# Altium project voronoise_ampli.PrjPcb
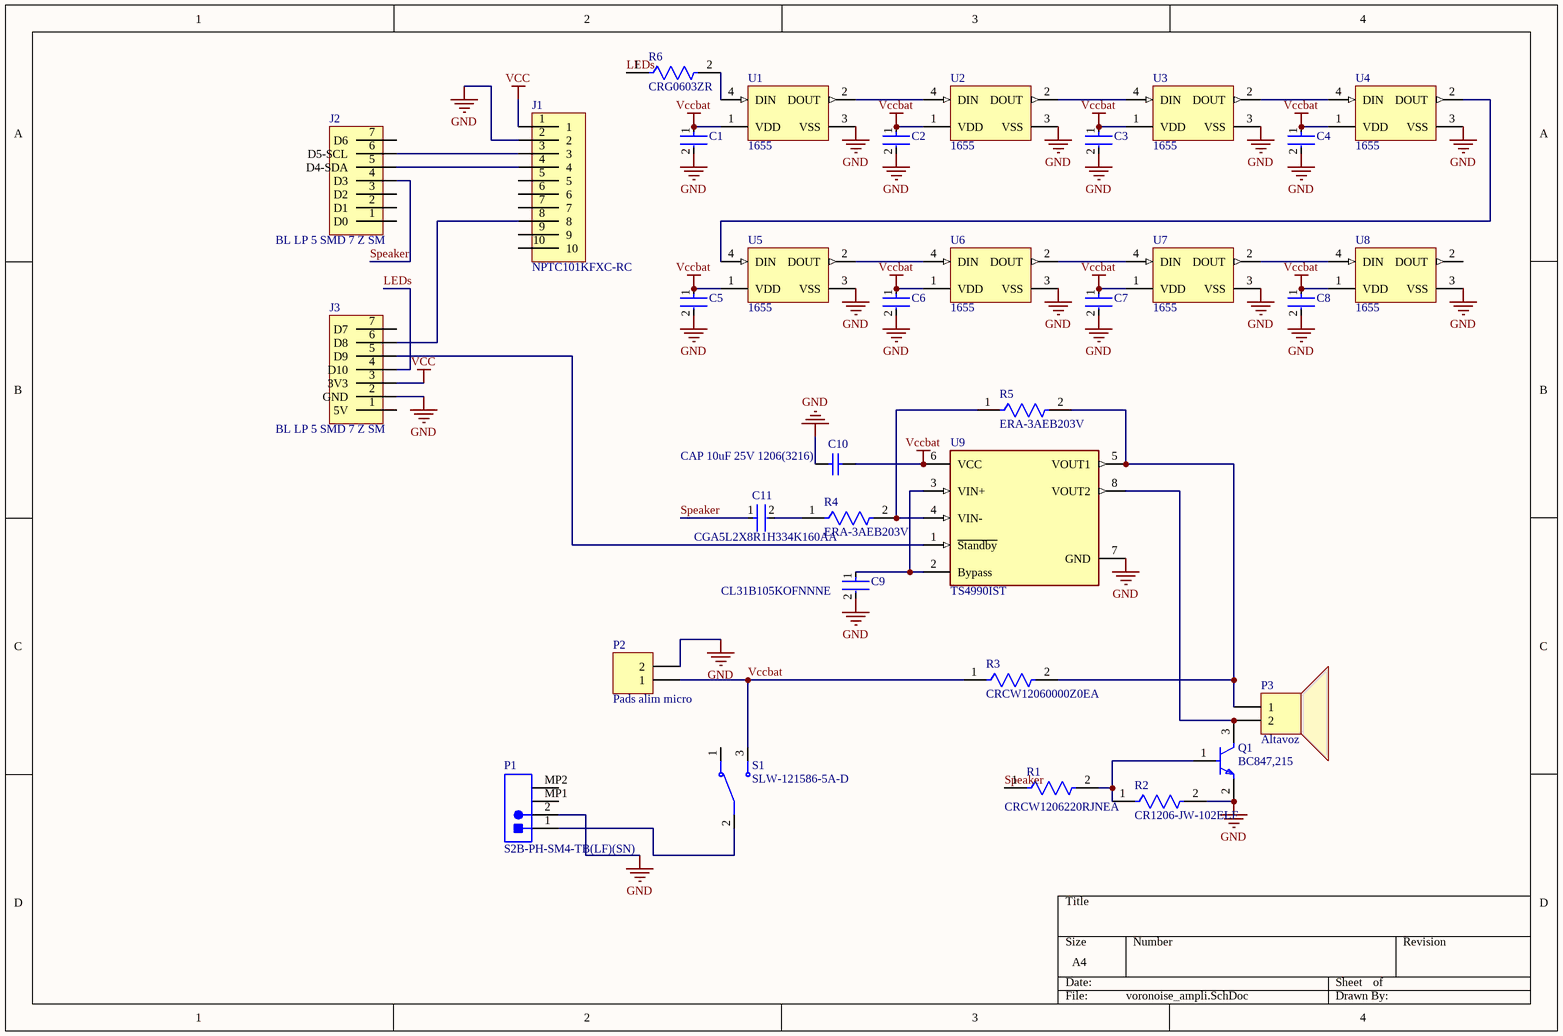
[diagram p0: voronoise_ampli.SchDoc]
1 sheet, 34 parts. Net scope: global (net labels, ports and power ports of the same name join across sheets).
Board file: voronoise_ampli.PcbDoc

## Sheet voronoise_ampli.SchDoc
size A4; SheetNumber: 1; SheetTotal: 1

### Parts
C1  C0603C104K4RACTU  [FP-C0603C-CF-MFG]  (value not drawn)
C2  C0603C104K4RACTU  [FP-C0603C-CF-MFG]  (value not drawn)
C3  C0603C104K4RACTU  [FP-C0603C-CF-MFG]  (value not drawn)
C4  C0603C104K4RACTU  [FP-C0603C-CF-MFG]  (value not drawn)
C5  C0603C104K4RACTU  [FP-C0603C-CF-MFG]  (value not drawn)
C6  C0603C104K4RACTU  [FP-C0603C-CF-MFG]  (value not drawn)
C7  C0603C104K4RACTU  [FP-C0603C-CF-MFG]  (value not drawn)
C8  C0603C104K4RACTU  [FP-C0603C-CF-MFG]  (value not drawn)
C9  CL31B105KOFNNNE  [FP-CL31-IPC_C]
C10  CAP 10uF 25V 1206(3216)  [CAPC1206(3216)190_N]
C11  CGA5L2X8R1H334K160AA  [FP-CGA5L-0_3-0_1-MFG]
J1  NPTC101KFXC-RC  [NPTC101KFXC-RC]
J2  BL LP 5 SMD 7 Z SM  [BL LP 5 SMD 7 Z SM]
J3  BL LP 5 SMD 7 Z SM  [BL LP 5 SMD 7 Z SM]
P1  S2B-PH-SM4-TB(LF)(SN)  [JST- S2B-PH-SM4-TB(LF)(SN)-2_V]
P2  Pads alim micro  [HDR1X2]
P3  Altavoz  [HDR1X2]
Q1  BC847,215  [FP-SOT23-MFG]
R1  CRCW1206220RJNEA  [FP-CRCW1206-e3-IPC_C]
R2  CR1206-JW-102ELF  [FP-CR1206-IPC_C]
R3  CRCW12060000Z0EA  [FP-CRCW1206-e3-IPC_C]
R4  ERA-3AEB203V  [FP-ERA3A-MFG]
R5  ERA-3AEB203V  [FP-ERA3A-MFG]
R6  CRG0603ZR  [FP-CRG0603-IPC_C]
S1  SLW-121586-5A-D  [SW_SLW-121586-5A-D]
U1  1655  [ADA-RGB-1655_V]
U2  1655  [ADA-RGB-1655_V]
U3  1655  [ADA-RGB-1655_V]
U4  1655  [ADA-RGB-1655_V]
U5  1655  [ADA-RGB-1655_V]
U6  1655  [ADA-RGB-1655_V]
U7  1655  [ADA-RGB-1655_V]
U8  1655  [ADA-RGB-1655_V]
U9  TS4990IST  [FP-MiniSO-8-IPC_C]

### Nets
GND: C1.2 C2.2 C3.2 C4.2 C5.2 C6.2 C7.2 C8.2 C9.2 C10.1 J1.2 J3.2(GND) P1.2 P2.2 Q1.2(E) R2.2 U1.3(VSS) U2.3(VSS) U3.3(VSS) U4.3(VSS) U5.3(VSS) U6.3(VSS) U7.3(VSS) U8.3(VSS) U9.7(GND)
VCC: J1.1 J3.3(3V3)
Vccbat: C1.1 C2.1 C3.1 C4.1 C5.1 C6.1 C7.1 C8.1 C10.2 P2.1 R3.1 S1.3 U1.1(VDD) U2.1(VDD) U3.1(VDD) U4.1(VDD) U5.1(VDD) U6.1(VDD) U7.1(VDD) U8.1(VDD) U9.6(VCC)
LEDs: J3.4(D10) R6.1
Speaker: C11.1 J2.4(D3) R1.1
NetC9_1: C9.1 U9.2(Bypass) U9.3(VIN+)
NetC11_2: C11.2 R4.1
NetJ1_3: J1.3 J2.6(D5-SCL)
NetJ1_4: J1.4 J2.5(D4-SDA)
NetJ1_8: J1.8 J3.6(D8)
NetJ3_5: J3.5(D9) U9.1(~{Standby})
NetP1_1: P1.1 S1.2
NetP3_1: P3.1 R3.2 R5.2 U9.5(VOUT1)
NetP3_2: P3.2 Q1.3(C) U9.8(VOUT2)
NetQ1_1: Q1.1(B) R1.2 R2.1
NetR4_2: R4.2 R5.1 U9.4(VIN-)
NetR6_2: R6.2 U1.4(DIN)
NetU1_2: U1.2(DOUT) U2.4(DIN)
NetU2_2: U2.2(DOUT) U3.4(DIN)
NetU3_2: U3.2(DOUT) U4.4(DIN)
NetU4_2: U4.2(DOUT) U5.4(DIN)
NetU5_2: U5.2(DOUT) U6.4(DIN)
NetU6_2: U6.2(DOUT) U7.4(DIN)
NetU7_2: U7.2(DOUT) U8.4(DIN)

Not connected (* = marked no-connect by the designer): J1 5 6 7 9 10; J2 1(D0) 2(D1) 3(D2) 7(D6); J3 1(5V) 7(D7); P1 MP1 MP2; S1 1; U8 2(DOUT)

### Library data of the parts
C1-C8 = CMP-2006-03811-3: Capacitor; Ceramic; Cap; .100uF; Tol 10%; SMT; Vol-Rtg 16V; X7R; Tape and Reel; Manufacturer: KEMET; Value: 0.10 μF; Temperature Coefficient: 30ppm/°C; Automotive Grade: Grade 1; Tolerance: 0.1; Description: C0603 0.10 μF X7R 30ppm/°C 10.00% 16 V
C9 = CMP-13271-000025-1: Cap Ceramic 1uF 16V X7R ±10% SMD 1206 +125°C Embossed T/R
C10 = CMP-1037-04981-1: CAP 10uF 25V -20% to +80% 1206 (3216 Metric) Thickness 1.9mm SMD; Case-EIA: 1206; Case-Metric: 3216
C11 = CMP-08246-001129-1: Cap Ceramic 330nF 50V X8R 10% Pad SMD 1206 +150°C Automotive T/R
J1 = NPTC101KFXC-RC: Sullins Connector Solutions 10 pin female header. SMD.
J2 J3 = BL LP 5 SMD 7 Z SM: Fischer elektronik 7 pin female header. SMD.
P1 = CMP-1755-00001-1: Male Header, Pitch 2 mm, 1 x 2 Position, Height 5.5 mm, -25 to 85 degC, RoHS, Tape and Reel; Current Rating: 3 A
P2 P3 = Header 2: Header, 2-Pin
Q1 = CMP-14406-000009-1: TRANS NPN 45V 0.1A SOT23; Manufacturer: Nexperia; Max Collector Current: 100mA; Hfe Testvce: 5V; Hfe Testic: 2mA; Number Of Npn: 1; Max Junction Temp: +150°C; Collector Base Voltage: 50V; Hfe Max: 800; Power Dissipation: 250mW; Emitter Base Voltage: 6V; Automotive Grade: Grade 0; Gain Bandwidth Product: 100MHz; Rthja Max: 500K/W; Collector Emitter Saturation Voltage: 200mV; Hfe Min: 110
R1 = CMP-1014-00058-3: RES Thick Film, 220Ω, 5%, 0.25W, 200ppm/°C, 1206; Voltage Rating: 200V; Max Power Dissipation: 250mW; Resistance: 220R
R2 = CMP-07231-001820-1: Thick Film Chip Resistors 1206 1kΩ 0.25W 5% 200ppm/°C; Voltage Rating: 200V; Resistance: 1kR; Power Rating: 250mW
R3 = CMP-2003-04857-2: RES Thick Film, 0Ω, 0.25W, 1206; Resistance: 0mR; Power Rating: 250mW; Temperature Coefficient: 100ppm/°C; Tolerance: 1%; Voltage Rating (DC): 200V
R4 R5 = CMP-2000-00946-2: RES SMD 20K OHM 0.1% 1/10W 0603; Max Power Dissipation: 100mW; Resistance: 20kR; Voltage Rating (DC): 75V; Temperature Coefficient: 25ppm/°C
R6 = CMP-03211-011415-1: RES SMD 0 OHM JUMPER 1/10W 0603; Voltage Rating: 50V; Resistance: 0mR; Power Rating: 100mW; Number of Resistors: 1; Tolerance: 0%; Temperature Coefficient: 100ppm/°C
U1-U8 = CMP-2000-05026-1: Intelligent Control LED Integrated Light Source, 3.5 to 5.3 V, -25 to 80 degC, 4-Pin SMD, RoHS, Tape and Reel; Manufacturer: Adafruit-Industries-LLC; Number of LEDs: 10; Configuration: Discrete; Utilized LED: WS2812(5050)
U9 = CMP-12130-000001-1: IC AMP AUDIO PWR 1.2W MONO 8MSOP; Manufacturer: STMicroelectronics; Gain Bandwidth: 1.5MHz; Standoff Height: 0mm; Max Junction Temp: +150°C; Min Supply Voltage: 2.2V; Power At Speaker R: 1.2W @ 8Ω; Number Of Channels: 1; Max Supply Voltage: 5.5V; Nominal Supply Current: 3.1-3.7mA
